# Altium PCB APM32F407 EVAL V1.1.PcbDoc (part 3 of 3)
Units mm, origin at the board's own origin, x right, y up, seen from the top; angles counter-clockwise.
Board outline 133.48 x 125.98 mm, 2 copper layers (Top Layer, Bottom Layer); 143 components, 208 nets, 809 pads, 486 vias.
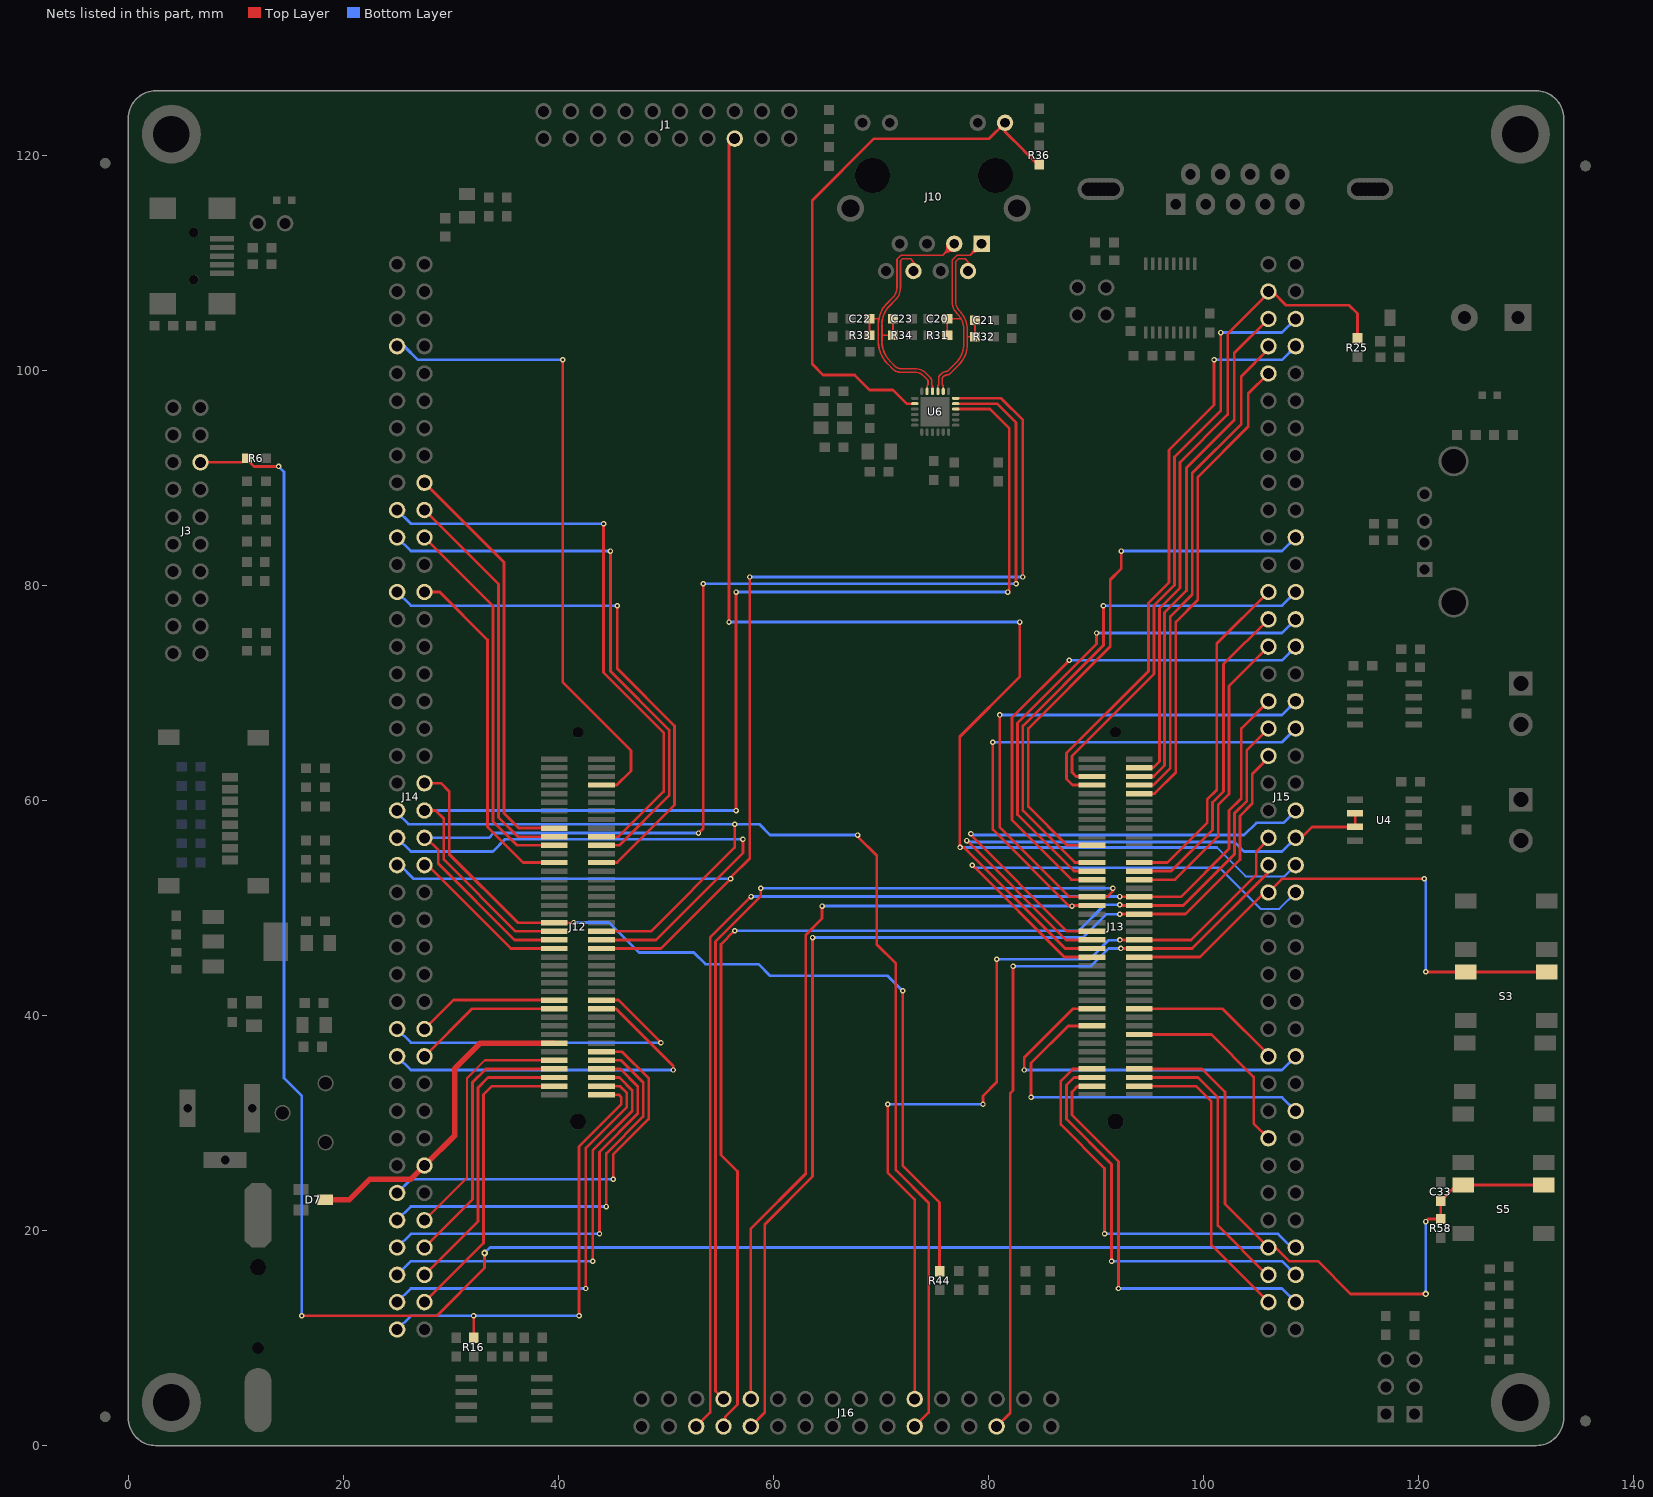
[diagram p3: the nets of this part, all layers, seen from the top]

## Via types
v1: diameter 0.508, hole 0.254, Top Layer to Bottom Layer, 294 vias
v2: diameter 0.61, hole 0.305, Top Layer to Bottom Layer, 172 vias
v3: diameter 0.406, hole 0.203, Top Layer to Bottom Layer, 17 vias
v4: diameter 0.6, hole 0.3, Top Layer to Bottom Layer, 3 vias

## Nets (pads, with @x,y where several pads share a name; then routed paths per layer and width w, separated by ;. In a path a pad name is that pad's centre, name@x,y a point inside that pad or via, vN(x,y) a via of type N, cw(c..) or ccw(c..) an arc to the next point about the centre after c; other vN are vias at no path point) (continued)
PE11_SMC_D8: J13.37 J15.37 J16.10 | length 101.3
  Top Layer w0.254: J16.10@57.888,1.778 59.182,3.072 59.182,20.574 63.627,25.019 v1(63.627,47.244) ; v1(92.202,49.403) 92.223,49.424 J13.37@94.005,49.424 98.319,49.424 103.378,54.483 103.378,58.547 104.521,59.69 104.521,62.463 106.021,63.963 J15.37@106.021,64.135
  Bottom Layer w0.254: v1(63.627,47.244) 88.773,47.244 90.932,49.403 v1(92.202,49.403)
PE12_SMC_D9: J13.36 J15.36 J16.9 | length 120.8
  Top Layer w0.254: J16.9@57.888,4.318 57.888,20.169 62.992,25.273 62.992,47.498 64.516,49.022 v1(64.516,50.165) ; v1(80.391,65.405) 80.391,57.277 87.444,50.224 J13.36@89.605,50.224
  Bottom Layer w0.254: v1(64.516,50.165) v1(87.757,50.165) ; v1(80.391,65.405) 107.291,65.405 J15.36@108.561,66.675
PE13_SMC_D10: J13.35 J15.35 J16.8 | length 110.3
  Top Layer w0.254: J16.8@55.348,1.778 55.499,1.929 55.499,2.667 56.642,3.81 56.642,25.503 55.118,27.027 55.118,46.609 v1(56.388,47.879) ; v1(92.202,50.292) 92.27,50.224 J13.35@94.005,50.224 98.103,50.224 102.87,54.991 102.87,58.801 104.013,59.944 104.013,64.667 J15.35@106.021,66.675
  Bottom Layer w0.254: v1(56.388,47.879) 88.392,47.879 90.805,50.292 v1(92.202,50.292)
PE14_SMC_D11: J13.34 J15.34 J16.7 | length 134.5
  Top Layer w0.254: J16.7@55.348,4.318 54.61,5.056 54.61,46.855 58.801,51.046 v1(58.801,51.816) ; v1(81.026,67.945) 81.026,57.531 87.533,51.024 J13.34@89.605,51.024 91.029,51.024 91.567,51.562 v1(91.567,51.816)
  Bottom Layer w0.254: v1(58.801,51.816) v1(91.567,51.816) ; v1(81.026,67.945) 107.291,67.945 J15.34@108.561,69.215
PE15_SMC_D12: J13.33 J15.33 J16.6 | length 112.9
  Top Layer w0.254: J16.6@52.808,1.778 54.102,3.072 54.102,47.244 v1(57.912,51.054) ; v1(92.202,51.054) 92.232,51.024 J13.33@94.005,51.024 97.887,51.024 102.362,55.499 102.362,59.055 103.505,60.198 103.505,66.699 J15.33@106.021,69.215
  Bottom Layer w0.254: v1(57.912,51.054) v1(92.202,51.054)
PF0_SDR_A10: J12.74 J14.74 | length 25.3
  Top Layer w0.254: J14.74@27.535,18.415 32.004,22.884 32.004,33.782 33.246,35.024 J12.74@39.605,35.024
PF1_SDR_A0: J12.75 J14.75 | length 39.5
  Top Layer w0.254: v1(43.18,17.145) 43.18,27.432 46.863,31.115 46.863,33.02 45.659,34.224 J12.75@44.005,34.224
  Bottom Layer w0.254: J14.75@24.995,15.875 26.265,17.145 v1(43.18,17.145)
PF2_SDR_A1: J12.76 J14.76 | length 26.9
  Top Layer w0.254: J14.76@27.535,15.875 32.512,20.852 32.512,33.274 33.462,34.224 J12.76@39.605,34.224
PF3_SDR_A2: J12.77 J14.77 | length 40.4
  Top Layer w0.254: v1(42.545,14.605) 42.545,27.686 46.355,31.496 46.355,32.766 45.697,33.424 J12.77@44.005,33.424
  Bottom Layer w0.254: J14.77@24.995,13.335 26.265,14.605 v1(42.545,14.605)
PF4_SDR_A3: J12.78 J14.78 | length 28.5
  Top Layer w0.254: J14.78@27.535,13.335 33.02,18.82 33.02,32.639 33.805,33.424 J12.78@39.605,33.424
PF5_SPI_CS: J12.79 J14.79 R16.2 | length 43.4
  Top Layer w0.254: R16.2@32.131,10.019 v1@32.131,12.065 ; v1(41.91,12.065) 41.91,27.813 45.847,31.75 45.847,32.385 45.608,32.624 J12.79@44.005,32.624
  Bottom Layer w0.254: J14.79@24.995,10.795 26.265,12.065 41.529,12.065 v1(41.91,12.065)
  other v1: 32.107,12.065
PF6_SDR_A4: J13.78 J15.78 | length 39.2
  Top Layer w0.254: J13.78@89.605,33.424 88.288,33.424 87.757,32.893 87.757,30.734 92.075,26.416 v1(92.075,14.605)
  Bottom Layer w0.254: v1(92.075,14.605) 107.291,14.605 J15.78@108.561,13.335
PF7_SDR_A5: J13.77 J15.77 | length 28.2
  Top Layer w0.254: J13.77@94.005,33.424 99.291,33.424 100.711,32.004 100.711,18.645 J15.77@106.021,13.335
PF8_SDR_A6: J13.76 J15.76 | length 38.4
  Top Layer w0.254: J13.76@89.605,34.224 87.945,34.224 87.249,33.528 87.249,30.353 91.44,26.162 v1(91.44,17.145)
  Bottom Layer w0.254: v1(91.44,17.145) 107.291,17.145 J15.76@108.561,15.875
PF9_SDR_A7: J13.75 J15.75 | length 26.6
  Top Layer w0.254: J13.75@94.005,34.224 99.483,34.224 101.322,32.385 101.322,20.447 105.894,15.875 J15.75@106.021,15.875
PF10_SDR_A8: J13.74 J15.74 | length 37.6
  Top Layer w0.254: J13.74@89.605,35.024 87.832,35.024 86.717,33.909 86.717,29.845 90.781,25.781 v1(90.781,19.685)
  Bottom Layer w0.254: v1(90.781,19.685) 106.91,19.685 108.18,18.415 J15.74@108.561,18.415
PF11_SDR_UDQM: J13.48 J15.48 | length 47.5
  Top Layer w0.254: v1(78.486,53.975) 87.037,45.424 J13.48@89.605,45.424
  Bottom Layer w0.203: 101.473,53.721 105.283,49.911 107.037,49.911 J15.48@108.561,51.435
  Bottom Layer w0.254: v1(78.486,53.975) 78.74,53.721 101.473,53.721 ; J15.48@108.077,51.435 J15.48@108.561,51.435
PF12_KEY3: J13.47 J15.47 S3.3 S3.4 | length 49.5
  Top Layer w0.254: J13.47@94.005,45.424 99.653,45.424 105.664,51.435 J15.47@106.021,51.435 107.291,52.705 v1(120.523,52.705) ; v1(120.65,44.069) 120.686,44.033 S3.4@124.393,44.033 S3.3@131.893,44.033
  Bottom Layer w0.254: v1(120.523,52.705) 120.65,52.578 v1(120.65,44.069)
PF13_CAMER_RST: J1.5 J13.46 J15.46 | length 144.4
  Top Layer w0.254: v1(55.856,76.581) 55.856,121.007 J1.5@56.388,121.539 ; v1@77.319,55.626 77.319,65.913 82.907,71.501 v1(82.907,76.581) ; v1(77.343,55.626) 77.724,55.626 87.126,46.224 J13.46@89.605,46.224
  Bottom Layer w0.203: 101.219,55.626 103.911,52.934 107.52,52.934 J15.46@108.561,53.975
  Bottom Layer w0.254: v1(55.856,76.581) v1(82.907,76.581) ; v1(77.343,55.626) 101.219,55.626
PF14_LCD_BK: J13.45 J15.45 J16.28 | length 71.5
  Top Layer w0.254: J16.28@80.748,1.778 82.018,3.048 82.018,32.766 82.272,33.02 v1(82.272,44.577) ; v1(92.305,46.228) 92.309,46.224 J13.45@94.005,46.224 98.929,46.224 106.021,53.316 J15.45@106.021,53.975
  Bottom Layer w0.254: v1(82.272,44.577) 89.511,44.577 91.162,46.228 v1(92.305,46.228)
PF15_485_EN: J13.44 J15.44 U4.2 U4.3 | length 54.2
  Top Layer w0.254: v1(77.978,56.261) 87.215,47.024 J13.44@89.605,47.024 ; J15.44@108.561,56.515 109.069,56.515 110.085,57.531 U4.3@114.091,57.531 U4.2@114.091,58.801
  Bottom Layer w0.254: v1(77.978,56.261) 78.105,56.134 102.87,56.134 103.759,55.245 107.291,55.245 J15.44@108.561,56.515
PG0_LCD_RS: J13.43 J15.43 J16.21 | length 82.2
  Top Layer w0.254: v1(70.612,31.75) 70.612,25.4 73.128,22.884 J16.21@73.128,4.318 ; v1(79.478,31.75) 79.478,32.512 80.748,33.782 v1(80.748,45.212) ; v1(92.212,47.024) J13.43@94.005,47.024 ; J13.43@94.411,47.024 98.84,47.024 104.902,53.086 104.902,55.245 106.021,56.364 J15.43@106.021,56.515
  Bottom Layer w0.254: v1(70.612,31.75) v1(79.478,31.75) ; v1(80.748,45.212) 89.384,45.212 91.162,46.99 v1@92.212,46.99
PG1_SDR_CLK: J13.42 J15.42 | length 46.3
  Top Layer w0.254: v1(78.359,56.896) 78.359,56.769 87.304,47.824 J13.42@89.605,47.824
  Bottom Layer w0.254: v1(78.359,56.896) 78.486,56.769 103.759,56.769 104.902,57.912 107.418,57.912 J15.42@108.561,59.055
PG2_SDR_D15: J13.9 J15.9 | length 44.9
  Top Layer w0.254: J13.9@94.005,60.624 95.422,60.624 97.409,62.611 97.409,76.581 99.441,78.613 99.441,90.043 104.14,94.742 104.14,97.814 J15.9@106.021,99.695
PG3_SDR_D0: J13.8 J15.8 | length 55.4
  Top Layer w0.254: J13.8@89.605,61.424 87.801,61.424 87.249,61.976 87.249,64.389 94.869,72.009 94.869,78.359 96.774,80.264 96.774,92.583 100.965,96.774 v1(100.965,100.965)
  Bottom Layer w0.254: v1(100.965,100.965) 107.291,100.965 J15.8@108.561,102.235
PG4_SDR_D1: J13.7 J15.7 | length 46.6
  Top Layer w0.254: J13.7@94.005,61.424 95.333,61.424 96.901,62.992 96.901,77.089 98.933,79.121 98.933,90.424 103.505,94.996 103.505,99.441 106.021,101.957 J15.7@106.021,102.235
PG5_SDR_D2: J13.6 J15.6 | length 56.1
  Top Layer w0.254: J13.6@89.605,62.224 88.144,62.224 87.757,62.611 87.757,64.135 95.377,71.755 95.377,78.105 97.282,80.01 97.282,91.948 101.6,96.266 v1(101.6,103.505)
  Bottom Layer w0.254: v1(101.6,103.505) 107.291,103.505 J15.6@108.561,104.775
PG6_SDR_D3: J13.5 J15.5 | length 48.3
  Top Layer w0.254: J13.5@94.005,62.224 95.347,62.224 96.369,63.246 96.369,77.47 98.401,79.502 98.401,90.932 102.846,95.377 102.846,101.6 J15.5@106.021,104.775
PG7_BUZ: J13.3 J15.3 R25.2 | length 61.4
  Top Layer w0.254: J13.3@94.005,63.024 95.282,63.024 95.885,63.627 95.885,77.851 97.79,79.756 97.79,91.44 102.235,95.885 102.235,103.378 106.021,107.164 J15.3@106.021,107.315 106.402,107.315 107.672,106.045 113.514,106.045 114.3,105.259 R25.2@114.3,102.983
PG8_SDR_D4: J12.7 J14.7 | length 60
  Top Layer w0.254: v1(40.386,100.965) 40.386,70.993 46.736,64.643 46.736,62.738 45.422,61.424 J12.7@44.005,61.424
  Bottom Layer w0.254: J14.7@24.995,102.235 25.654,102.235 26.924,100.965 v1(40.386,100.965)
PG9: J12.40 J14.40 R44.1 | length 83.4
  Top Layer w0.254: J14.40@27.535,61.595 29.083,61.595 29.845,60.833 29.845,54.991 36.212,48.624 J12.40@39.605,48.624 41.385,48.624 v1(41.402,48.641) ; v1(72.009,42.291) 72.009,26.035 75.438,22.606 R44.1@75.438,16.217
  Bottom Layer w0.254: v1(41.402,48.641) 44.704,48.641 47.498,45.847 52.578,45.847 53.657,44.767 58.61,44.767 59.69,43.688 70.612,43.688 v1(72.009,42.291)
PG10_LCD_CS: J12.41 J14.41 J16.22 | length 119.9
  Top Layer w0.254: J12.41@44.005,47.824 48.586,47.824 56.388,55.626 v1(56.388,57.785) ; v1(67.818,56.769) 67.818,56.642 69.596,54.864 69.596,46.609 71.374,44.831 71.374,25.63 74.422,22.582 74.422,3.072 J16.22@73.128,1.778
  Bottom Layer w0.254: J14.41@24.995,59.055 24.995,58.825 26.035,57.785 v1(56.388,57.785) 58.674,57.785 59.69,56.769 v1(67.818,56.769)
PG11_RMII_TX_EN: J12.42 J14.42 U6.16 | length 114.5
  Top Layer w0.254: J14.42@27.535,59.055 28.575,59.055 29.337,58.293 29.337,54.483 35.996,47.824 J12.42@39.605,47.824 ; v1(56.515,59.055) v1(56.515,79.375) ; U6.16@76.933,96.389 80.141,96.389 81.915,94.615 81.915,79.502 v1(81.788,79.375)
  Bottom Layer w0.254: J14.42@27.535,59.055 v1(56.515,59.055) ; v1(56.515,79.375) v1(81.788,79.375)
PG12: J12.43 J14.43 | length 50.9
  Top Layer w0.254: J12.43@44.005,47.024 49.056,47.024 57.15,55.118 v1(57.15,56.388)
  Bottom Layer w0.254: J14.43@24.995,56.515 26.265,55.245 33.909,55.245 35.052,56.388 v1(57.15,56.388)
PG13_RMII_TXD0: J12.44 J14.44 U6.17 | length 116.2
  Top Layer w0.254: J14.44@27.535,56.515 27.686,56.515 28.829,55.372 28.829,54.102 35.907,47.024 J12.44@39.605,47.024 ; v1(53.023,56.959) 53.467,57.404 v1(53.467,80.137) ; U6.17@76.933,96.889 80.784,96.889 82.55,95.123 v1(82.55,80.137)
  Bottom Layer w0.254: J14.44@27.535,56.515 33.528,56.515 33.972,56.959 v1(53.023,56.959) ; v1(53.467,80.137) v1(82.55,80.137)
PG14_RMII_TXD1: J12.45 J14.45 U6.18 | length 122.1
  Top Layer w0.254: J12.45@44.001,46.228 49.53,46.228 v1(56.007,52.705) 56.007,52.832 57.785,54.61 v1(57.785,80.772) ; U6.18@76.933,97.389 81.173,97.389 83.185,95.377 v1(83.185,80.772)
  Bottom Layer w0.254: J14.45@24.995,53.975 25.273,53.975 26.543,52.705 v1(56.007,52.705) ; v1(57.785,80.772) v1(83.185,80.772)
PG15_SDR_LDQM: J12.46 J14.46 | length 15.3
  Top Layer w0.254: J14.46@27.535,53.975 27.813,53.975 35.564,46.224 J12.46@39.605,46.224
PH2: J13.65 J15.65 | length 18.6
  Top Layer w0.254: J13.65@94.005,38.224 100.714,38.224 104.648,34.29 104.648,29.948 J15.65@106.021,28.575
PH3_SDR_A9: J13.64 J15.64 | length 35.4
  Top Layer w0.254: v1(83.947,32.385) 83.947,35.56 87.411,39.024 J13.64@89.605,39.024
  Bottom Layer w0.254: v1(83.947,32.385) 107.291,32.385 J15.64@108.561,31.115
PH4: J13.60 J15.60 | length 35.1
  Top Layer w0.254: v1(83.312,34.925) 83.312,36.068 87.868,40.624 J13.60@89.605,40.624
  Bottom Layer w0.254: v1(83.312,34.925) 107.291,34.925 J15.60@108.561,36.195
PH5_SDR_CKE: J13.59 J15.59 | length 13.9
  Top Layer w0.254: J13.59@94.005,40.624 101.743,40.624 106.021,36.346 J15.59@106.021,36.195
PH6: J13.30 J15.30 | length 48.4
  Top Layer w0.254: v1(87.503,73.025) 82.169,67.691 82.169,58.166 87.711,52.624 J13.30@89.605,52.624
  Bottom Layer w0.254: v1(87.503,73.025) 107.291,73.025 J15.30@108.561,74.295
PH7: J13.29 J15.29 | length 28.6
  Top Layer w0.254: J13.29@94.005,52.624 97.328,52.624 101.346,56.642 101.346,59.563 102.362,60.579 102.362,70.636 J15.29@106.021,74.295
PH8_SDR_D8: J13.28 J15.28 | length 48.1
  Top Layer w0.254: J13.28@89.605,53.424 87.927,53.424 82.677,58.674 82.677,67.183 90.043,74.549 v1(90.043,75.565)
  Bottom Layer w0.254: v1(90.043,75.565) 107.291,75.565 J15.28@108.561,76.835
PH9: J13.27 J15.27 | length 30.1
  Top Layer w0.254: J13.27@94.005,53.424 96.985,53.424 100.814,57.253 100.814,59.817 100.838,59.817 101.854,60.833 101.854,72.668 J15.27@106.021,76.835
PH10_SDR_D9: J13.26 J15.26 | length 49
  Top Layer w0.254: J13.26@89.605,54.224 88.016,54.224 83.185,59.055 83.185,66.929 90.678,74.422 v1(90.678,78.105)
  Bottom Layer w0.254: v1(90.678,78.105) 107.291,78.105 J15.26@108.561,79.375
PH11: J13.25 J15.25 | length 31.7
  Top Layer w0.254: J13.25@94.005,54.224 96.642,54.224 100.33,57.912 100.33,60.071 101.219,60.96 101.219,74.573 J15.25@106.021,79.375
PH12: J13.22 J15.22 | length 51.5
  Top Layer w0.254: J13.22@89.605,55.824 87.305,55.824 83.693,59.436 83.693,66.675 91.313,74.295 91.313,80.518 92.329,81.534 v1(92.329,83.185)
  Bottom Layer w0.254: v1(92.329,83.185) 107.291,83.185 J15.22@108.561,84.455
PH13_SDR_D5: J12.18 J14.18 | length 39
  Top Layer w0.254: J14.18@27.535,89.535 34.925,82.145 34.925,58.801 36.302,57.424 J12.18@39.605,57.424
PH14: J12.19 J14.19 | length 54.5
  Top Layer w0.254: J12.19@44.005,56.624 45.575,56.624 49.784,60.833 49.784,66.294 44.196,71.882 v1(44.196,85.725)
  Bottom Layer w0.254: J14.19@24.995,86.995 26.265,85.725 v1(44.196,85.725)
PH15_SDR_D6: J12.20 J14.20 | length 37.4
  Top Layer w0.254: J14.20@27.535,86.995 34.417,80.113 34.417,58.42 36.213,56.624 J12.20@39.605,56.624
PI0: J12.21 J14.21 | length 53.6
  Top Layer w0.254: J12.21@44.005,55.824 45.664,55.824 50.292,60.452 50.292,66.548 44.831,72.009 v1(44.831,83.185)
  Bottom Layer w0.254: J14.21@24.995,84.455 26.265,83.185 v1(44.831,83.185)
PI1: J12.22 J14.22 | length 35.7
  Top Layer w0.254: J14.22@27.535,84.455 33.909,78.081 33.909,58.039 36.124,55.824 J12.22@39.605,55.824
PI2: J12.25 J14.25 | length 50.8
  Top Layer w0.254: J12.25@44.005,54.224 45.461,54.224 50.8,59.563 50.8,66.929 45.466,72.263 v1(45.466,78.105)
  Bottom Layer w0.254: J14.25@24.995,79.375 26.265,78.105 v1(45.466,78.105)
PI3_SDR_D7: J12.26 J14.26 | length 32.7
  Top Layer w0.254: J14.26@27.535,79.375 28.956,79.375 33.401,74.93 33.401,57.531 36.708,54.224 J12.26@39.605,54.224
PI4: J12.57 J14.57 | length 32.2
  Top Layer w0.254: J12.57@44.005,41.424 45.571,41.424 v1(49.53,37.465)
  Bottom Layer w0.254: J14.57@24.995,38.735 26.265,37.465 28.067,37.465 v1(49.53,37.465)
PI5: J12.58 J14.58 | length 13.2
  Top Layer w0.254: J14.58@27.535,38.735 27.559,38.735 30.248,41.424 J12.58@39.605,41.424
PI6: J12.59 J14.59 | length 35.5
  Top Layer w0.254: J12.59@44.005,40.624 45.355,40.624 50.673,35.306 v1(50.673,34.925)
  Bottom Layer w0.254: J14.59@24.995,36.195 26.265,34.925 v1(50.673,34.925)
PI7_SDR_NWE: J12.60 J14.60 | length 13.9
  Top Layer w0.254: J14.60@27.535,36.195 31.964,40.624 J12.60@39.605,40.624
PI8_SDR_NCAS: J12.69 J14.69 | length 36.8
  Top Layer w0.254: J12.69@44.005,36.624 45.926,36.624 48.387,34.163 48.387,30.353 45.085,27.051 v1(45.085,24.765)
  Bottom Layer w0.254: J14.69@24.995,23.495 26.265,24.765 28.575,24.765 v1(45.085,24.765)
PI9_SDR_NRAS: J12.71 J14.71 | length 38
  Top Layer w0.254: J12.71@43.688,35.824 J12.71@44.005,35.824 45.837,35.824 47.879,33.782 47.879,30.607 44.45,27.178 v1(44.45,22.225)
  Bottom Layer w0.254: J14.71@24.995,20.955 26.265,22.225 v1(44.45,22.225)
PI10_SDR_NCS: J12.72 J14.72 | length 23.6
  Top Layer w0.203: J14.72@27.535,20.955 31.496,24.916 31.496,34.163 33.157,35.824 J12.72@39.605,35.824
PI11_SDR_BA: J12.73 J14.73 | length 38.6
  Top Layer w0.254: v1(43.815,19.685) 43.815,27.305 47.371,30.861 47.371,33.401 45.748,35.024 J12.73@44.005,35.024
  Bottom Layer w0.254: J14.73@24.995,18.415 26.265,19.685 v1(43.815,19.685)
RESET: C33.2 J3.15 J13.73 J15.73 R6.1 R58.2 S5.3 S5.4 | length 242.5
  Top Layer w0.254: J3.15@6.707,91.44 10.531,91.44 10.912,91.821 11.674,91.059 v1(13.97,91.059) ; v1(16.129,12.065) 28.677,12.064 33.123,16.51 v2(33.123,17.907) ; J13.73@94.005,35.024 99.85,35.024 101.981,32.893 101.981,22.455 J15.73@106.021,18.415 106.68,18.415 107.95,17.145 110.617,17.145 113.665,14.097 v4(120.65,14.097) ; v1(120.65,20.828) 120.89,21.068 R58.2@122.047,21.068 C33.2@122.047,22.747 123.521,24.221 S5.4@124.139,24.221 S5.3@131.639,24.221
  Bottom Layer w0.254: v1(13.97,91.059) 14.478,90.551 14.478,34.163 16.129,32.512 v1(16.129,12.065) ; v2(33.123,17.907) 33.631,18.415 J15.73@106.021,18.415 ; v4(120.65,14.097) v1(120.65,20.828)
SPEED_LED: J10.9 R36.1 U6.2 | length 52.3
  Top Layer w0.254: U6.2@73.133,96.889 72.378,96.889 71.096,98.171 68.937,98.171 67.54,99.568 64.619,99.568 63.603,100.584 63.603,115.8 69.342,121.539 80.06,121.539 J10.9@81.531,123.01 81.531,122.177 83.288,120.42 83.288,120.41 R36.1@84.558,119.14
TPRX_N: C23.2 J10.6 R34.2 U6.22 | length 21.1
  Top Layer w0.152: C23.2@71.11,104.775 R34.2@71.11,103.251 70.08,103.251 ; J10.6@72.836,109.884 ccw(c72.779,110.104) 73.006,110.104 ; J10.6@73.006,109.22 73.006,110.104 ; J10.6@73.176,109.884 cw(c73.233,110.104) 73.006,110.104 ; U6.22@74.783,98.039 74.783,98.552 74.698,98.637 74.698,99.06 ccw(c74.368,99.06) 74.601,99.293 74.177,99.718 ccw(c73.128,98.668) 73.128,100.152 71.779,100.152 cw(c71.779,100.759) 71.35,100.33 70.824,100.856 cw(c72.62,102.652) 70.08,102.652 70.08,103.251 ; 70.08,103.251 70.08,104.267 cw(c72.533,104.267) 70.798,106.001 71.322,106.525 ccw(c70.152,107.696) 71.807,107.696 71.807,110.185 71.985,110.363 72.747,110.363 73.006,110.104
TPRX_P: C22.2 J10.3 R33.2 U6.23 | length 29.4
  Top Layer w0.152: R33.2@68.923,103.251 C22.2@68.923,104.775 69.72,104.775 69.726,104.78 ; U6.23@74.283,98.039 74.283,98.552 74.368,98.637 74.368,99.06 73.944,99.484 ccw(c73.128,98.668) 73.128,99.822 71.779,99.822 cw(c71.779,100.759) 71.117,100.097 70.59,100.623 cw(c72.62,102.652) 69.75,102.652 69.75,104.267 cw(c72.533,104.267) 70.565,106.235 71.089,106.759 ccw(c70.152,107.696) 71.477,107.696 71.477,110.322 71.848,110.693 75.744,110.693 ; J10.3@76.127,111.713 cw(c74.813,111.624) 75.744,110.693 ; J10.3@76.279,111.724 cw(c75.257,111.654) 75.981,110.93 cw(c76.705,110.206) J10.3@76.775,111.228 ; J10.3@76.431,111.734 cw(c75.701,111.684) 76.218,111.167 cw(c76.735,110.65) J10.3@76.785,111.38 ; J10.3@76.764,111.076 ccw(c76.675,109.762) 75.744,110.693 ; J10.3@76.811,111.76 75.744,110.693
TPTX_N: C21.2 J10.2 R32.2 U6.20 | length 18.5
  Top Layer w0.152: U6.20@75.783,98.039 75.783,98.552 75.698,98.637 75.698,99.314 75.794,99.41 cw(c76.176,99.027) 76.176,99.568 ccw(c76.176,99.898) 76.409,99.665 77.19,100.445 ccw(c75.16,102.474) 78.03,102.474 78.03,103.124 ; J10.2@77.916,109.884 ccw(c77.859,110.104) 78.086,110.104 ; J10.2@78.086,109.22 78.086,110.104 ; J10.2@78.256,109.884 cw(c78.313,110.104) 78.086,110.104 ; C21.2@78.73,104.648 R32.2@78.73,103.124 78.03,103.124 ; 78.03,103.124 78.03,103.75 ccw(c75.532,103.75) 77.298,105.516 cw(c78.169,106.387) 76.938,106.387 76.938,110.109 77.192,110.363 77.827,110.363 78.086,110.104
TPTX_P: C20.2 J10.1 R31.2 U6.21 | length 24.9
  Top Layer w0.152: U6.21@75.283,98.039 75.283,98.552 75.368,98.637 75.368,99.314 cw(c75.698,99.314) 75.465,99.547 75.56,99.643 cw(c76.176,99.027) 76.176,99.898 76.956,100.678 ccw(c75.16,102.474) 77.7,102.474 77.7,103.75 ccw(c75.532,103.75) 77.065,105.283 cw(c78.169,106.387) 76.608,106.387 76.608,110.246 77.055,110.693 78.284,110.693 ; R31.2@76.162,103.251 C20.2@76.162,104.775 77.402,104.775 77.404,104.773 ; J10.1@78.667,111.713 cw(c77.353,111.624) 78.284,110.693 ; J10.1@78.819,111.724 cw(c77.797,111.654) 78.521,110.93 cw(c79.245,110.206) J10.1@79.315,111.228 ; J10.1@78.971,111.734 cw(c78.241,111.684) 78.758,111.167 cw(c79.275,110.65) J10.1@79.325,111.38 ; J10.1@79.304,111.076 ccw(c79.215,109.762) 78.284,110.693 ; J10.1@79.351,111.76 78.284,110.693
VBAT_IN: D7.3 J12.68 J14.68 | length 31
  Top Layer w0.508: D7.3@18.272,22.86 20.55,22.86 22.455,24.765 26.265,24.765 J14.68@27.535,26.035 27.559,26.035 30.353,28.829 30.353,35.052 32.725,37.424 J12.68@39.605,37.424
pads on no net: BT1.0 H1.1 H2.1 H3.1 H4.1 J1.13 J1.15 J2.6 J2.7 J2.8 J2.9 J3.17 J3.19 J5. J5.4 J9.3 J10.7 J10.15 J10.16 J12.81 J12.82 J13.81 J13.82 U1.7 U1.8 U1.9 U1.10 U6.10 X1.2 X1.4
copper on no net: | length 62.8
  Top Layer w0.3: -0.909,2.667 ccw(c-2.159,2.667) -0.909,2.667 ; -0.909,119.253 ccw(c-2.159,119.253) -0.909,119.253 ; 136.759,2.286 ccw(c135.509,2.286) 136.759,2.286 ; 136.759,118.999 ccw(c135.509,118.999) 136.759,118.999
  Bottom Layer w0.3: -0.919,2.677 ccw(c-2.169,2.677) -0.919,2.677 ; -0.919,119.263 ccw(c-2.169,119.263) -0.919,119.263 ; 136.749,2.296 ccw(c135.499,2.296) 136.749,2.296 ; 136.749,119.009 ccw(c135.499,119.009) 136.749,119.009

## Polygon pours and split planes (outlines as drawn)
GND on Top Layer "Top Overlay-No Net" (solid, remove dead copper, pour order 4): 3.302,125.603 3.048,125.603 2.413,125.603 0.381,123.571 0.381,122.555 0.381,2.286 2.286,0.381 3.556,0.381 8.763,0.381 126.365,0.381 131.064,0.381 133.096,2.413 133.096,4.191 133.096,123.698 131.191,125.603
GND on Bottom Layer "Top Overlay-No Net" (solid, remove dead copper, pour order 6): 2.413,125.603 0.381,123.571 0.381,2.286 2.286,0.381 131.064,0.381 133.096,2.413 133.096,123.698 131.191,125.603

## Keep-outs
Keep-Out Layer:
  circle w0.127: c136.906,123.952 r1
  circle w0.127: c136.906,7.239 r1
  lines w0.1: 0,0.889 0,125.095 ; 0,2.54 ccw(c2.54,2.54) 2.54,0 130.937,0 ccw(c130.937,2.54) 133.477,2.54 133.477,123.444 ccw(c130.937,123.444) 130.937,125.984 2.54,125.984 ccw(c2.54,123.444) 0,123.444 0,2.54
  lines w0.127: -5,125.96 -5,0 0,0 0,125.96 -4.976,125.96 ; 138.453,125.96 133.477,125.96 133.477,0 138.477,0 138.477,125.96

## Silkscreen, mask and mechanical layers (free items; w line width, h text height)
Top Overlay:
  drawing of 4311 lines, arcs and shapes, not listed
  text "APM32F407 EVAL V1.1" at 10.668,121.793 h2.5
  text "USB_5V" at 12.065,118.618 h1.52
  text "PB9" at 38.989,116.84 h1.52 r90
  text "PB8" at 41.656,116.84 h1.52 r90
  text "PE6" at 44.196,116.84 h1.52 r90
  text "PE5" at 46.863,116.84 h1.52 r90
  text "PB6" at 49.276,116.84 h1.52 r90
  text "PE4" at 51.816,116.84 h1.52 r90
  text "PC9" at 54.356,116.84 h1.52 r90
  text "PC8" at 56.896,116.84 h1.52 r90
  text "PC7" at 59.436,116.84 h1.52 r90
  text "PC6" at 61.976,116.84 h1.52 r90
  text "RS232" at 119.761,116.459 h2
  text "GND" at 38.989,113.157 h1.52 r90
  text "PA4" at 41.656,113.157 h1.52 r90
  text "NC" at 44.196,113.157 h1.52 r90
  text "NC" at 46.863,113.157 h1.52 r90
  text "PB7" at 49.276,113.157 h1.52 r90
  text "PA6" at 51.816,113.157 h1.52 r90
  text "PA8" at 54.356,113.157 h1.52 r90
  text "PF13" at 56.896,113.157 h1.52 r90
  text "PA0" at 59.436,113.157 h1.52 r90
  text "5V" at 61.976,113.157 h1.52 r90
  text "CAMERA" at 46.736,110.236 h2
  text "3V3" at 20.193,109.474 h1.52
  text "3V3" at 29.21,109.474 h1.52
  text "GND" at 101.473,109.347 h1.52
  text "GND" at 110.236,109.347 h1.52
  text "USB_Device" at 18.796,107.061 h1.52 r90
  text "5V" at 20.066,106.934 h1.52
  text "5V" at 29.21,106.934 h1.52
  text "PG7" at 101.473,106.807 h1.52
  text "GND" at 110.236,106.807 h1.52
  text "GND" at 20.066,104.394 h1.52
  text "GND" at 29.21,104.394 h1.52
  text "PG6" at 101.473,104.267 h1.52
  text "PG5" at 110.236,104.267 h1.52
  text "PG8" at 20.066,101.854 h1.52
  text "PC6" at 29.21,101.854 h1.52
  text "PG4" at 101.473,101.727 h1.52
  text "PG3" at 110.236,101.727 h1.52
  text "PC7" at 20.066,99.314 h1.52
  text "PC8" at 29.21,99.314 h1.52
  text "PG2" at 101.473,99.187 h1.52
  text "PD15" at 110.236,99.187 h1.52
  text "PC9" at 20.066,96.774 h1.52
  text "PA8" at 29.21,96.774 h1.52
  text "U1_RX" at 89.027,96.647 h2 r90
  text "U1_TX" at 91.567,96.647 h2 r90
  text "PD14" at 101.473,96.647 h1.52
  text "PD13" at 110.236,96.647 h1.52
  text "JTAG" at 10.541,95.758 h2
  text "PA9" at 20.066,94.234 h1.52
  text "PA11" at 29.21,94.234 h1.52
  text "PD12" at 101.473,94.107 h1.52
  text "PD11" at 110.236,94.107 h1.52
  text "PA10" at 20.066,91.694 h1.52
  text "PA12" at 29.21,91.567 h1.52
  text "PD10" at 101.473,91.567 h1.52
  text "PD9" at 110.236,91.567 h1.52
  text "PH13" at 29.21,89.154 h1.52
  text "PA13" at 20.066,89.027 h1.52
  text "PD8" at 101.473,88.9 h1.52
  text "PB13" at 110.236,88.9 h1.52
  text "USB_HOST" at 117.094,87.376 h1.52 r90
  text "PH14" at 20.066,86.614 h1.52
  text "PH15" at 29.21,86.487 h1.52
  text "PB15" at 101.473,86.487 h1.52
  text "PB12" at 110.236,86.487 h1.52
  text "PI0" at 20.066,83.947 h1.52
  text "PI1" at 29.21,83.947 h1.52
  text "PB14" at 101.473,83.82 h1.52
  text "PH12" at 110.236,83.82 h1.52
  text "GND" at 29.21,81.534 h1.52
  text "GND" at 20.066,81.407 h1.52
  text "GND" at 101.473,81.28 h1.52
  text "GND" at 110.236,81.28 h1.52
  text "PI2" at 20.066,78.994 h1.52
  text "PI3" at 29.21,78.994 h1.52
  text "PH11" at 101.473,78.867 h1.52
  text "PH10" at 110.236,78.867 h1.52
  text "PA14" at 20.066,76.454 h1.52
  text "PA15" at 29.21,76.454 h1.52
  text "PH9" at 101.473,76.327 h1.52
  text "PH8" at 110.236,76.327 h1.52
  text "PC10" at 20.066,73.914 h1.52
  text "PC11" at 29.21,73.914 h1.52
  text "PH7" at 101.473,73.787 h1.52
  text "PH6" at 110.236,73.787 h1.52
  text "CANH" at 121.793,73.025 h1.52 r270
  text "PC12" at 20.066,71.374 h1.52
  text "PD0" at 29.21,71.374 h1.52
  text "PB11" at 101.473,71.247 h1.52
  text "PB10" at 109.982,71.247 h1.52
  text "PD1" at 20.066,68.834 h1.52
  text "PD2" at 29.21,68.834 h1.52
  text "CANL" at 121.793,68.834 h1.52 r270
  text "PE15" at 101.473,68.707 h1.52
  text "PE14" at 109.982,68.707 h1.52
  text "PD3" at 20.066,66.294 h1.52
  text "PD4" at 29.21,66.294 h1.52
  text "PE13" at 101.473,66.167 h1.52
  text "PE12" at 109.982,66.167 h1.52
  text "PD5" at 20.066,63.754 h1.52
  text "PD6" at 29.21,63.754 h1.52
  text "PE11" at 101.473,63.627 h1.52
  text "PE10" at 110.236,63.627 h1.52
  text "485B" at 121.793,61.849 h1.52 r270
  text "PD7" at 20.066,61.214 h1.52
  text "PG9" at 29.21,61.214 h1.52
  text "PE9" at 101.473,61.214 h1.52
  text "PE8" at 110.236,61.214 h1.52
  text "PG10" at 20.066,58.674 h1.52
  text "PG11" at 29.21,58.674 h1.52
  text "PE7" at 101.473,58.547 h1.52
  text "PG1" at 110.236,58.547 h1.52
  text "485A" at 121.793,57.912 h1.52 r270
  text "PG12" at 20.066,56.134 h1.52
  text "PG13" at 29.21,56.134 h1.52
  text "PG0" at 101.473,56.007 h1.52
  text "PF15" at 109.982,56.007 h1.52
  text "PG14" at 20.066,53.594 h1.52
  text "PG15" at 29.21,53.594 h1.52
  text "PF14" at 101.473,53.467 h1.52
  text "PF13" at 110.236,53.467 h1.52
  text "PB3" at 20.066,51.054 h1.52
  text "PB4" at 29.21,51.054 h1.52
  text "PF12" at 101.473,50.927 h1.52
  text "PF11" at 110.236,50.927 h1.52
  text "PB5" at 20.066,48.514 h1.52
  text "PB6" at 29.21,48.514 h1.52
  text "PB2" at 101.473,48.387 h1.52
  text "PB1" at 110.236,48.387 h1.52
  text "PB7" at 20.066,45.974 h1.52
  text "BOOT0" at 29.21,45.974 h1.52
  text "KEY4" at 119.231,45.974 h2 r90
  text "PB0" at 101.473,45.847 h1.52
  text "PC5" at 110.236,45.847 h1.52
  text "PB8" at 20.066,43.434 h1.52
  text "PB9" at 29.21,43.434 h1.52
  text "PC4" at 101.473,43.307 h1.52
  text "PA7" at 110.236,43.307 h1.52
  text "PE0" at 20.066,40.894 h1.52
  text "PE1" at 29.21,40.894 h1.52
  text "PA6" at 101.473,40.767 h1.52
  text "PA5" at 110.236,40.767 h1.52
  text "KEY3" at 119.236,39.878 h2 r90
  text "PI4" at 20.066,38.354 h1.52
  text "PI5" at 29.21,38.354 h1.52
  text "PA4" at 101.473,38.227 h1.52
  text "PA3" at 110.236,38.227 h1.52
  text "ON" at 18.923,36.322 h1.52 r270
  text "PI6" at 20.066,35.814 h1.52
  text "PI7" at 29.21,35.814 h1.52
  text "PH5" at 101.473,35.687 h1.52
  text "PH4" at 110.236,35.687 h1.52
  text "KEY2" at 119.236,33.528 h2 r90
  text "GND" at 20.066,33.274 h1.52
  text "GND" at 29.21,33.274 h1.52
  text "GND" at 101.473,33.147 h1.52
  text "GND" at 110.236,33.147 h1.52
  text "PE3" at 29.21,30.734 h1.52
  text "PE2" at 20.066,30.607 h1.52
  text "GND" at 101.473,30.607 h1.52
  text "PH3" at 110.236,30.607 h1.52
  text "PE4" at 20.066,28.194 h1.52
  text "PE5" at 29.21,28.067 h1.52
  text "PH2" at 101.473,28.067 h1.52
  text "PA2" at 110.236,28.067 h1.52
  text "OFF" at 18.796,27.305 h1.52 r270
  text "KEY1" at 119.236,27.051 h2 r90
  text "VBAT" at 29.21,25.654 h1.52
  text "PE6" at 20.066,25.527 h1.52
  text "PA1" at 101.473,25.4 h1.52
  text "PA0" at 110.236,25.4 h1.52
  text "DC_5V" at 1.524,23.114 h2
  text "PI8" at 20.066,23.114 h1.52
  text "PC13" at 29.21,23.114 h1.52
  text "PC3" at 101.473,22.987 h1.52
  text "PC2" at 110.236,22.987 h1.52
  text "PI9" at 20.066,20.574 h1.52
  text "PI10" at 29.21,20.574 h1.52
  text "PC1" at 101.473,20.447 h1.52
  text "PC0" at 110.236,20.447 h1.52
  text "RESET" at 119.253,19.304 h2 r90
  text "PI11" at 20.066,18.034 h1.52
  text "PF0" at 29.21,18.034 h1.52
  text "RST" at 101.473,17.907 h1.52
  text "PF10" at 110.236,17.907 h1.52
  text "PF1" at 20.066,15.494 h1.52
  text "PF2" at 29.21,15.494 h1.52
  text "PF9" at 101.473,15.367 h1.52
  text "PF8" at 110.236,15.367 h1.52
  text "LED3" at 121.158,15.24 h2
  text "FSMC 液晶接口" at 59.944,14.859 h2
  text "PF3" at 20.066,12.954 h1.52
  text "PF4" at 29.21,12.954 h1.52
  text "PF7" at 101.473,12.827 h1.52
  text "PF6" at 110.236,12.827 h1.52
  text "LED2" at 121.171,11.684 h2
  text "PF5" at 20.066,10.414 h1.52
  text "3V3" at 101.473,10.287 h1.52
  text "3V3" at 110.236,10.287 h1.52
  text "GND" at 48.26,9.779 h1.52 r90
  text "PD10" at 50.8,9.779 h1.52 r90
  text "PD8" at 53.34,9.779 h1.52 r90
  text "PE14" at 55.88,9.779 h1.52 r90
  text "PE12" at 58.42,9.779 h1.52 r90
  text "PE10" at 60.96,9.779 h1.52 r90
  text "PE8" at 63.5,9.779 h1.52 r90
  text "PD1" at 66.04,9.779 h1.52 r90
  text "PD15" at 68.58,9.779 h1.52 r90
  text "PD4" at 71.12,9.779 h1.52 r90
  text "PG0" at 73.66,9.779 h1.52 r90
  text "PG9" at 76.073,9.779 h1.52 r90
  text "PD6" at 78.74,9.779 h1.52 r90
  text "PE2" at 81.28,9.779 h1.52 r90
  text "5V" at 83.82,9.779 h1.52 r90
  text "3V3" at 86.36,9.779 h1.52 r90
  text "LED1" at 121.406,8.255 h2
  text "VDD" at 109.093,7.62 h1.52
  text "VDD" at 112.522,7.62 h1.52
  text "PE3" at 48.26,6.096 h1.52 r90
  text "PD9" at 50.8,6.096 h1.52 r90
  text "PE15" at 53.34,6.096 h1.52 r90
  text "PE13" at 55.88,6.096 h1.52 r90
  text "PE11" at 58.42,6.096 h1.52 r90
  text "PE9" at 60.96,6.096 h1.52 r90
  text "PE7" at 63.5,6.096 h1.52 r90
  text "PD0" at 66.04,6.096 h1.52 r90
  text "PD14" at 68.58,6.096 h1.52 r90
  text "PD5" at 71.12,6.096 h1.52 r90
  text "PG10" at 73.66,6.096 h1.52 r90
  text "PD7" at 76.073,6.096 h1.52 r90
  text "PD3" at 78.74,6.096 h1.52 r90
  text "PF14" at 81.28,6.096 h1.52 r90
  text "GND" at 83.82,6.096 h1.52 r90
  text "GND" at 86.36,6.096 h1.52 r90
  text "BT0" at 109.347,5.08 h1.52
  text "BT1" at 112.903,5.08 h1.52
  text "GND" at 108.966,2.54 h1.52
  text "GND" at 112.522,2.54 h1.52
Mechanical 1:
  circle w0.127: c-3.032,123.999 r1
  circle w0.127: c-3.159,7.667 r1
